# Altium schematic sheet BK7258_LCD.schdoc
size 331 x 191 mm
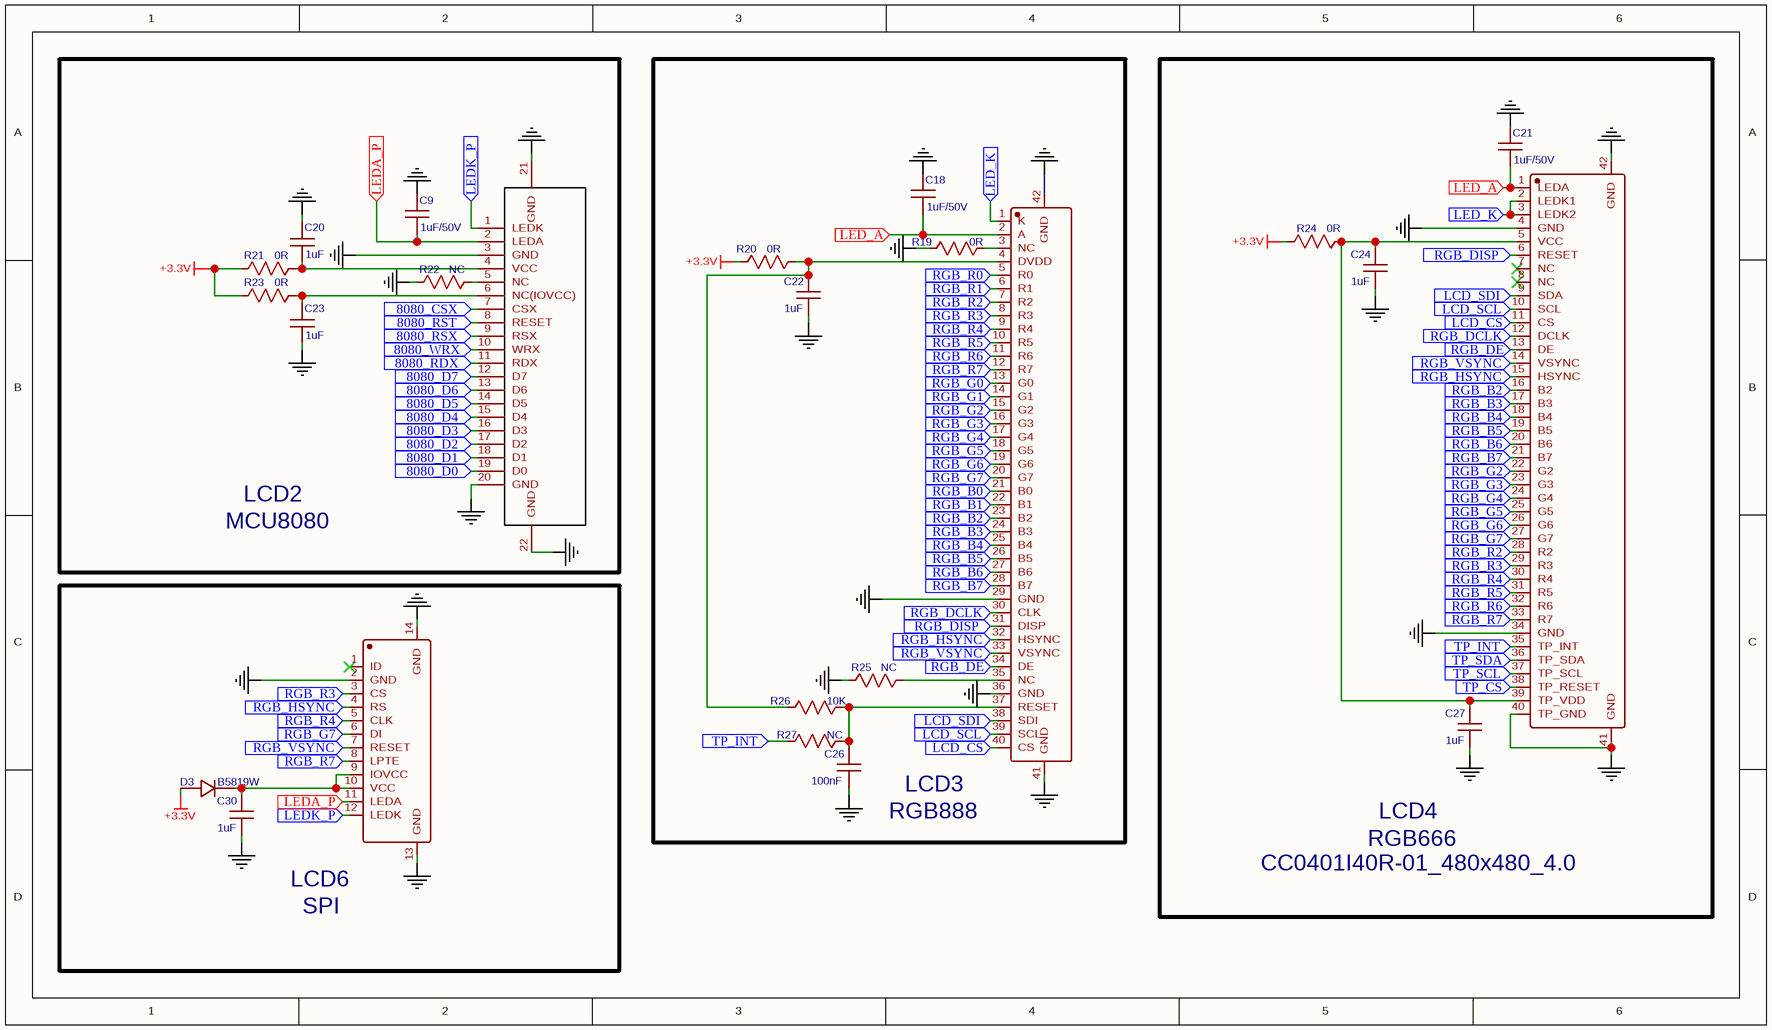
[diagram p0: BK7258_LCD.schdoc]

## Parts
C9  1uF/50V  [C0603]
C18  1uF/50V  [C0603]
C20  1uF  [C0402]
C21  1uF/50V  [C0603]
C22  1uF  [C0402]
C23  1uF  [C0402]
C24  1uF  [C0402]
C26  100nF  [C0402]
C27  1uF  [C0402]
C30  1uF  [C0402]
D3  B5819W  [SOD-123]
LCD2  MCU8080  [FPC_0.5MM_20PIN_UPDATED2]
LCD3  RGB888  [FPC_0.5MM_40PIN_UPDATED2]
LCD4  RGB666  [FPC_0.5MM_40PIN_AA]
LCD6  SPI  [FPC14PIN-0.5MM_UPDATED]
R19  0R  [R0402]
R20  0R  [R0402]
R21  0R  [R0402]
R22  NC  [R0402]
R23  0R  [R0402]
R24  0R  [R0402]
R25  NC  [R0402]
R26  10K  [R0402]
R27  NC  [R0402]

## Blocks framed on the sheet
CC0401I40R-01_480x480_4.0: C21 C24 C27 LCD4 R24

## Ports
8080_CSX (in), 8080_D0 (in), 8080_D1 (in), 8080_D2 (in), 8080_D3 (in), 8080_D4 (in), 8080_D5 (in), 8080_D6 (in), 8080_D7 (in), 8080_RDX (in), 8080_RST (in), 8080_RSX (in), 8080_WRX (in), LCD_CS (in), LCD_SCL (in), LCD_SDI (in), LED_A (in), LED_K (in), LEDA_P (in), LEDK_P (in), RGB_B0 (in), RGB_B1 (in), RGB_B2 (in), RGB_B3 (in), RGB_B4 (in), RGB_B5 (in), RGB_B6 (in), RGB_B7 (in), RGB_DCLK (in), RGB_DE (in), RGB_DISP (in), RGB_G0 (in), RGB_G1 (in), RGB_G2 (in), RGB_G3 (in), RGB_G4 (in), RGB_G5 (in), RGB_G6 (in), RGB_G7 (in), RGB_HSYNC (in), RGB_R0 (in), RGB_R1 (in), RGB_R2 (in), RGB_R3 (in), RGB_R4 (in), RGB_R5 (in), RGB_R6 (in), RGB_R7 (in), RGB_VSYNC (in), TP_CS (in), TP_INT (in), TP_SCL (in), TP_SDA (in)

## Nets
+3.3V: D3.2(A) R20.1 R21.1 R23.1 R24.1
GGND: C9.1 C18.1 C20.2 C21.1 C22.2 C23.1 C24.2 C26.2 C27.2 C30.2 LCD2.3(GND) LCD2.20(GND) LCD2.21(GND) LCD2.22(GND) LCD3.29(GND) LCD3.36(GND) LCD3.41(GND) LCD3.42(GND) LCD4.4(GND) LCD4.34(GND) LCD4.40(TP_GND) LCD4.41(GND) LCD4.42(GND) LCD6.2(GND) LCD6.13(GND) LCD6.14(GND) R19.1 R22.1 R25.1
8080_CSX: LCD2.7(CSX) ; port 8080_CSX
8080_D0: LCD2.19(D0) ; port 8080_D0
8080_D1: LCD2.18(D1) ; port 8080_D1
8080_D2: LCD2.17(D2) ; port 8080_D2
8080_D3: LCD2.16(D3) ; port 8080_D3
8080_D4: LCD2.15(D4) ; port 8080_D4
8080_D5: LCD2.14(D5) ; port 8080_D5
8080_D6: LCD2.13(D6) ; port 8080_D6
8080_D7: LCD2.12(D7) ; port 8080_D7
8080_RDX: LCD2.11(RDX) ; port 8080_RDX
8080_RST: LCD2.8(RESET) ; port 8080_RST
8080_RSX: LCD2.9(RSX) ; port 8080_RSX
8080_WRX: LCD2.10(WRX) ; port 8080_WRX
LCD_CS: LCD3.40(CS) LCD4.11(CS) ; port LCD_CS
LCD_SCL: LCD3.39(SCL) LCD4.10(SCL) ; port LCD_SCL
LCD_SDI: LCD3.38(SDI) LCD4.9(SDA) ; port LCD_SDI
LED_A: C18.2 C21.2 LCD3.2(A) LCD4.1(LEDA) ; port LED_A
LED_K: LCD3.1(K) LCD4.2(LEDK1) LCD4.3(LEDK2) ; port LED_K
LEDA_P: C9.2 LCD2.2(LEDA) LCD6.11(LEDA) ; port LEDA_P
LEDK_P: LCD2.1(LEDK) LCD6.12(LEDK) ; port LEDK_P
RGB_B0: LCD3.21(B0) ; port RGB_B0
RGB_B1: LCD3.22(B1) ; port RGB_B1
RGB_B2: LCD3.23(B2) LCD4.16(B2) ; port RGB_B2
RGB_B3: LCD3.24(B3) LCD4.17(B3) ; port RGB_B3
RGB_B4: LCD3.25(B4) LCD4.18(B4) ; port RGB_B4
RGB_B5: LCD3.26(B5) LCD4.19(B5) ; port RGB_B5
RGB_B6: LCD3.27(B6) LCD4.20(B6) ; port RGB_B6
RGB_B7: LCD3.28(B7) LCD4.21(B7) ; port RGB_B7
RGB_DCLK: LCD3.30(CLK) LCD4.12(DCLK) ; port RGB_DCLK
RGB_DE: LCD3.34(DE) LCD4.13(DE) ; port RGB_DE
RGB_DISP: LCD3.31(DISP) LCD4.6(RESET) ; port RGB_DISP
RGB_G0: LCD3.13(G0) ; port RGB_G0
RGB_G1: LCD3.14(G1) ; port RGB_G1
RGB_G2: LCD3.15(G2) LCD4.22(G2) ; port RGB_G2
RGB_G3: LCD3.16(G3) LCD4.23(G3) ; port RGB_G3
RGB_G4: LCD3.17(G4) LCD4.24(G4) ; port RGB_G4
RGB_G5: LCD3.18(G5) LCD4.25(G5) ; port RGB_G5
RGB_G6: LCD3.19(G6) LCD4.26(G6) ; port RGB_G6
RGB_G7: LCD3.20(G7) LCD4.27(G7) LCD6.6(DI) ; port RGB_G7
RGB_HSYNC: LCD3.32(HSYNC) LCD4.15(HSYNC) LCD6.4(RS) ; port RGB_HSYNC
RGB_R0: LCD3.5(R0) ; port RGB_R0
RGB_R1: LCD3.6(R1) ; port RGB_R1
RGB_R2: LCD3.7(R2) LCD4.28(R2) ; port RGB_R2
RGB_R3: LCD3.8(R3) LCD4.29(R3) LCD6.3(CS) ; port RGB_R3
RGB_R4: LCD3.9(R4) LCD4.30(R4) LCD6.5(CLK) ; port RGB_R4
RGB_R5: LCD3.10(R5) LCD4.31(R5) ; port RGB_R5
RGB_R6: LCD3.11(R6) LCD4.32(R6) ; port RGB_R6
RGB_R7: LCD3.12(R7) LCD4.33(R7) LCD6.8(LPTE) ; port RGB_R7
RGB_VSYNC: LCD3.33(VSYNC) LCD4.14(VSYNC) LCD6.7(RESET) ; port RGB_VSYNC
TP_CS: LCD4.38(TP_RESET) ; port TP_CS
TP_INT: LCD4.35(TP_INT) R27.1 ; port TP_INT
TP_SCL: LCD4.37(TP_SCL) ; port TP_SCL
TP_SDA: LCD4.36(TP_SDA) ; port TP_SDA
NetC20_1: C20.1 LCD2.4(VCC) R21.2
NetC22_1: C22.1 LCD3.4(DVDD) R20.2 R26.1
NetC23_2: C23.2 LCD2.6(NC(IOVCC)) R23.2
NetC24_1: C24.1 C27.1 LCD4.5(VCC) LCD4.39(TP_VDD) R24.2
NetC26_1: C26.1 LCD3.37(RESET) R26.2 R27.2
NetC30_1: C30.1 D3.1(K) LCD6.9(IOVCC) LCD6.10(VCC)
NetLCD2_5: LCD2.5(NC) R22.2
NetLCD3_3: LCD3.3(NC) R19.2
NetLCD3_35: LCD3.35(NC) R25.2

Not connected (* = marked no-connect by the designer): LCD4 7(NC)* 8(NC)*; LCD6 1(ID)*

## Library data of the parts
C9 C18 C21 = 1uF/50V: BOM_Manufacturer: SAMSUNG(三星); Manufacturer Part: CL10A105KB8NNNC
C20 C22-C24 C27 C30 = 1uF: Manufacturer Part: CL05A105KO5NNNC; BOM_Manufacturer: SAMSUNG(三星)
C26 = 100nF: BOM_Manufacturer: Walsin(华新科)
D3 = B5819W: BOM_Manufacturer: MDD; Contributor: LCSC
LCD2 = MCU8080: BOM_Manufacturer: JS(钜硕电子); BOM_Manufacturer Part: AFC01-S20FCA-00; Contributor: guogen.le
LCD3 = RGB888: BOM_Manufacturer: JS(钜硕电子); BOM_Manufacturer Part: AFC01-S40FCA-00; Contributor: guogen.le
LCD4 = RGB666: BOM_Manufacturer: JS(钜硕电子); BOM_Manufacturer Part: AFC01-S40FCA-00; Contributor: qunshan.xu
LCD6 = SPI: BOM_Manufacturer: HDGC（华德共创）; BOM_Manufacturer Part: 0.5K-1.5-12PWB; Contributor: jian.shi1
R19-R21 R23 R24 = 0R: Manufacturer Part: 0402WGF0000TCE; BOM_Manufacturer: UNI-ROYAL(厚声); nameAlias: Value(Ω); Contributor: LCEDA_Lib
R22 R25 R27 = NC: Manufacturer Part: 0402WGF0000TCE; BOM_Manufacturer: UNI-ROYAL(厚声); nameAlias: Value(Ω); Contributor: LCEDA_Lib
R26 = 10K: BOM_Manufacturer: UNI-ROYAL(厚声); nameAlias: Value(Ω); Contributor: LCEDA_Lib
